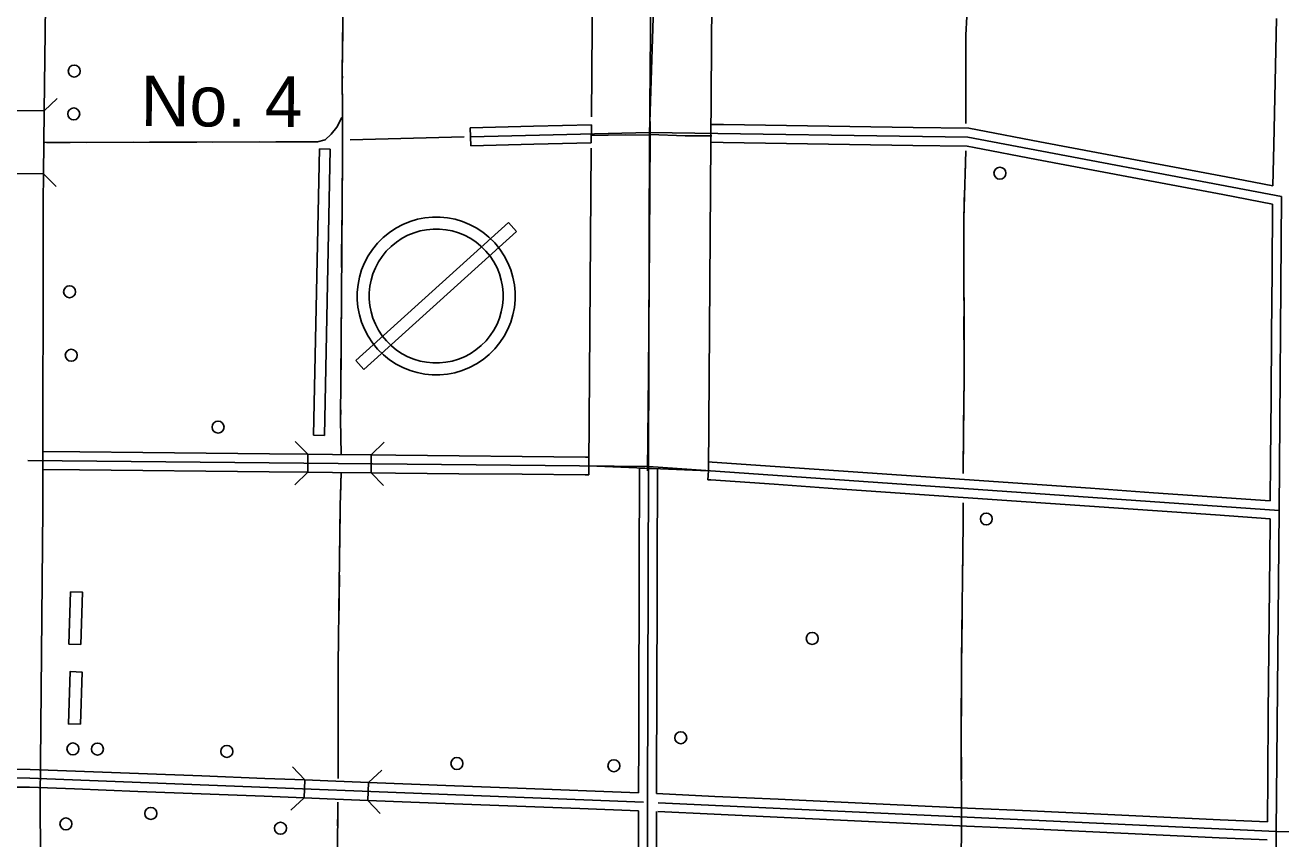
# Model space of a CAD drawing. Extents: x -4306 to 3843, y 131 to 8341.
# Drawn here: x -255 to 1424, y 1864 to 2952 of the extents above; entities that cross this region are included whole.
import ezdxf

# ---------------------------------------------------------------- set-up
doc = ezdxf.new("R2010")
doc.units = 0
for name, color, linetype in [('10', 7, 'Continuous'), ('31', 7, 'Continuous'), ('32', 7, 'Continuous'), ('33', 7, 'Continuous'), ('34', 7, 'Continuous'), ('38', 7, 'Continuous'), ('46', 7, 'Continuous'), ('52', 7, 'Continuous'), ('53', 7, 'Continuous'), ('55', 7, 'Continuous'), ('56', 7, 'Continuous'), ('57', 7, 'Continuous'), ('58', 7, 'Continuous'), ('62', 7, 'Continuous')]:
    doc.layers.add(name, color=color, linetype=linetype)

msp = doc.modelspace()

# ---------------------------------------------------------------- linework, layer by layer
at = {"layer": '10'}
for p, q in [((-229, 2837.7), (-269, 2838.1)), ((-229.9, 2753.2), (-229, 2837.2)), ((-269.9, 2754), (-229.9, 2753.6))]:
    msp.add_line(p, q, dxfattribs=at)
for points in [[(-226.6, 3049.5), (-229, 2837.2)], [(-229.9, 2753.2), (-230.3, 2716.3), (-231, 2305.2), (-234.2, 1917.5), (-233.4, 1758), (-238.7, 1599), (-240.3, 1434.8), (-238.9, 1200.9), (-242.2, 1053.5), (-244.1, 861.8), (-243.5, 732.4), (-254.4, 657.4), (-262.5, 621.4), (-265.5, 597.6), (-272.4, 440.2), (-274.5, 304.9), (-274.4, 293.9)]]:
    msp.add_lwpolyline(points, dxfattribs=at)
at = {"layer": '31'}
for p, q in [((566.1, 2166.4), (566.3, 2250.9)), ((566.3, 2250.9), (566.3, 2250.9)), ((590.1, 2166.3), (590.3, 2250.8)), ((565.9, 2081.9), (566.1, 2166.4)), ((589.9, 2081.9), (590.1, 2166.3)), ((-247.9, 1956.9), (-272.1, 1957.2)), ((-187.4, 1954.6), (-247.9, 1956.9)), ((-102.9, 1951.3), (-187.4, 1954.6)), ((-248.5, 1932.9), (-272.4, 1933.2)), ((-188.3, 1930.6), (-248.5, 1932.9)), ((-103.9, 1927.3), (-188.3, 1930.6)), ((65.9, 1944.7), (65.9, 1944.7)), ((119.3, 1942.7), (65.9, 1944.7)), ((118.4, 1918.7), (119.3, 1942.7)), ((150.3, 1941.5), (119.3, 1942.7)), ((204.6, 1939.4), (150.3, 1941.5)), ((203.6, 1915.4), (204.5, 1939.4)), ((204.5, 1939.4), (319.2, 1934.9)), ((319.2, 1934.9), (403.6, 1931.7)), ((565.4, 1925.4), (403.6, 1931.7)), ((118.6, 1918.7), (65, 1920.8)), ((149.4, 1917.5), (118.4, 1918.7)), ((203.6, 1915.4), (149.4, 1917.5)), ((318.3, 1910.9), (203.6, 1915.4)), ((402.7, 1907.7), (318.3, 1910.9)), ((487.1, 1904.4), (402.7, 1907.7)), ((565.4, 1901.4), (487.1, 1904.4))]:
    msp.add_line(p, q, dxfattribs=at)
for points in [[(579.9, 2808.9), (592.5, 3199.4), (592.3, 3209.3), (595.4, 3430.4)], [(577.4, 1912.9), (578.6, 2361.9), (579.9, 2808.9)], [(566.6, 2335.4), (566.6, 2360)], [(566.6, 2360), (590.6, 2359), (590.6, 2335.3)], [(566.3, 2250.9), (566.6, 2335.4)], [(590.6, 2335.3), (590.3, 2250.8)], [(565.6, 1997.4), (565.9, 2081.9)], [(589.9, 2081.9), (589.4, 1924.4)], [(565.4, 1925.4), (565.6, 1997.4)], [(-18.5, 1948), (-102.9, 1951.3)], [(65.9, 1944.7), (-18.5, 1948)], [(-103.9, 1927.3), (-19.4, 1924)], [(-19.4, 1924), (65, 1920.8)]]:
    msp.add_lwpolyline(points, dxfattribs=at)
at = {"layer": '32'}
for p, q in [((1418.2, 2961.3), (1416.3, 2876.8)), ((1416.3, 2876.8), (1414.4, 2792.4)), ((340.7, 2802.9), (579.9, 2808.9)), ((579.9, 2808.9), (1005.6, 2802.5)), ((662.1, 2819.7), (678.8, 2819.4)), ((678.8, 2819.4), (763.3, 2818.2)), ((763.3, 2818.2), (847.7, 2816.9)), ((847.7, 2816.9), (932.2, 2815.6)), ((932.2, 2815.6), (1006.8, 2814.5)), ((1006.8, 2814.5), (1018.6, 2812.2)), ((1018.6, 2812.2), (1101.6, 2796.5)), ((662, 2795.7), (678.4, 2795.4)), ((678.4, 2795.4), (762.9, 2794.2)), ((762.9, 2794.2), (847.4, 2792.9)), ((847.4, 2792.9), (931.9, 2791.6)), ((931.9, 2791.6), (1004.4, 2790.5)), ((1004.4, 2790.5), (1014.1, 2788.6)), ((1005.6, 2802.5), (1424.9, 2723.1)), ((1014.1, 2788.6), (1097.1, 2772.9)), ((1101.6, 2796.5), (1184.6, 2780.8)), ((1414.4, 2792.4), (1413.2, 2737.5)), ((1097.1, 2772.9), (1180.1, 2757.2)), ((1184.6, 2780.8), (1267.6, 2765.1)), ((1180.1, 2757.2), (1263.1, 2741.5)), ((1267.6, 2765.1), (1350.6, 2749.4)), ((1263.1, 2741.5), (1346.2, 2725.8)), ((1350.6, 2749.4), (1413.2, 2737.5)), ((1346.2, 2725.8), (1412.8, 2713.1)), ((1424.9, 2723.1), (1421.6, 2303.3)), ((1412.8, 2713.1), (1412.1, 2623.2)), ((1412.1, 2623.2), (1411.4, 2538.8)), ((1411.4, 2538.8), (1410.8, 2454.3)), ((1410.8, 2454.3), (1410.1, 2369.8)), ((578.6, 2361.9), (-250.7, 2370.1)), ((-181.5, 2381.5), (-230.8, 2381.9)), ((-97, 2380.6), (-181.5, 2381.5)), ((-12.5, 2379.8), (-97, 2380.6)), ((71.9, 2378.9), (-12.5, 2379.8)), ((123.4, 2378.4), (71.9, 2378.9)), ((123.4, 2378.4), (123.2, 2354.4)), ((156.4, 2378.1), (123.4, 2378.4)), ((208.1, 2377.6), (156.4, 2378.1)), ((208.1, 2377.6), (207.9, 2353.6)), ((240.9, 2377.3), (208.1, 2377.6)), ((325.4, 2376.4), (240.9, 2377.3)), ((409.9, 2375.6), (325.4, 2376.4)), ((494.4, 2374.7), (409.9, 2375.6)), ((499, 2374.7), (494.4, 2374.7)), ((499, 2374.7), (498.9, 2362.7)), ((658.8, 2368.4), (658.7, 2356.3)), ((663.8, 2368), (658.8, 2368.4)), ((748.1, 2362.1), (663.8, 2368)), ((1410.1, 2369.8), (1409.7, 2316.2)), ((-181.8, 2357.5), (-230.9, 2357.9)), ((-97.3, 2356.6), (-181.8, 2357.5)), ((-12.8, 2355.8), (-97.3, 2356.6)), ((71.7, 2354.9), (-12.8, 2355.8)), ((123.2, 2354.4), (71.7, 2354.9)), ((156.2, 2354.1), (123.2, 2354.4)), ((207.9, 2353.6), (156.2, 2354.1)), ((240.7, 2353.3), (207.9, 2353.6)), ((325.2, 2352.4), (240.7, 2353.3)), ((409.6, 2351.6), (325.2, 2352.4)), ((494.1, 2350.7), (409.6, 2351.6)), ((498.8, 2350.7), (494.1, 2350.7)), ((498.9, 2362.7), (498.8, 2350.7)), ((1421.6, 2303.3), (578.6, 2361.9)), ((658.7, 2356.3), (657.9, 2344.4)), ((832.4, 2356.3), (748.1, 2362.1)), ((916.7, 2350.4), (832.4, 2356.3)), ((1001, 2344.6), (916.7, 2350.4)), ((662.2, 2344.1), (657.9, 2344.4)), ((746.5, 2338.2), (662.2, 2344.1)), ((830.8, 2332.3), (746.5, 2338.2)), ((1085.3, 2338.7), (1001, 2344.6)), ((1169.6, 2332.9), (1085.3, 2338.7)), ((915, 2326.5), (830.8, 2332.3)), ((999.3, 2320.6), (915, 2326.5)), ((1083.6, 2314.8), (999.3, 2320.6)), ((1253.8, 2327), (1169.6, 2332.9)), ((1338.1, 2321.1), (1253.8, 2327)), ((1409.7, 2316.2), (1338.1, 2321.1)), ((1167.9, 2308.9), (1083.6, 2314.8)), ((1252.2, 2303.1), (1167.9, 2308.9)), ((1336.5, 2297.2), (1252.2, 2303.1)), ((1421.6, 2303.3), (1417.7, 1873.9)), ((1409.5, 2292.1), (1336.5, 2297.2)), ((1409.4, 2285.3), (1408.7, 2200.8)), ((1409.5, 2292.1), (1409.4, 2285.3)), ((1408.7, 2200.8), (1407.9, 2116.3)), ((1407.9, 2116.3), (1407.1, 2031.9)), ((1407.1, 2031.9), (1406.3, 1947.4)), ((-248.2, 1944.9), (-1090.3, 1954.4)), ((1406.3, 1947.4), (1405.8, 1886.5)), ((572, 1913.1), (-248.2, 1944.9)), ((667.4, 1920.7), (589.4, 1924.4)), ((751.8, 1916.8), (667.4, 1920.7)), ((836.2, 1912.9), (751.8, 1916.8)), ((565.4, 1901.4), (565.4, 1828.4)), ((577.4, 1912.9), (577.5, 1509.2)), ((589.4, 1900.3), (589.4, 1828.4)), ((666.3, 1896.8), (591.1, 1900.3)), ((1417.7, 1873.9), (591.7, 1912.3)), ((750.7, 1892.9), (666.3, 1896.8)), ((920.6, 1909), (836.2, 1912.9)), ((1005, 1905.1), (920.6, 1909)), ((1089.4, 1901.2), (1005, 1905.1)), ((1173.8, 1897.2), (1089.4, 1901.2)), ((1258.2, 1893.3), (1173.8, 1897.2)), ((835.1, 1888.9), (750.7, 1892.9)), ((919.5, 1885), (835.1, 1888.9)), ((1003.9, 1881.1), (919.5, 1885)), ((1088.3, 1877.2), (1003.9, 1881.1)), ((1342.6, 1889.4), (1258.2, 1893.3)), ((1405.8, 1886.5), (1342.6, 1889.4)), ((1172.7, 1873.3), (1088.3, 1877.2)), ((1257.1, 1869.4), (1172.7, 1873.3)), ((1341.5, 1865.4), (1257.1, 1869.4)), ((1405.6, 1862.5), (1341.5, 1865.4)), ((1417.7, 1873.9), (1414, 1460.6)), ((1849.1, 1865.2), (1417.7, 1873.9))]:
    msp.add_line(p, q, dxfattribs=at)
at = {"layer": '33'}
for p, q in [((582.4, 3039.2), (580.3, 2843.7)), ((580.3, 2843.7), (580.7, 2804)), ((580.7, 2804), (579.8, 2663.9)), ((580.7, 2806.1), (627.8, 2804.5)), ((627.8, 2804.5), (663.4, 2804.3)), ((579.8, 2663.9), (578.5, 2485.6)), ((578.5, 2485.6), (577.4, 2356.1))]:
    msp.add_line(p, q, dxfattribs=at)
at = {"layer": '34'}
for p, q in [((547.4, 2805.6), (502.1, 2804.7)), ((580.6, 2805.3), (547.4, 2805.6))]:
    msp.add_line(p, q, dxfattribs=at)
at = {"layer": '38'}
for points in [[(106.6, 2395.6), (123.4, 2378.4)], [(208.1, 2377.6), (225.2, 2394.4)], [(123.2, 2354.4), (106.1, 2337.6)], [(224.7, 2336.4), (207.9, 2353.6)], [(103, 1960.3), (119.3, 1942.7)], [(204.5, 1939.4), (222.1, 1955.7)], [(118.4, 1918.7), (100.8, 1902.4)], [(219.9, 1897.8), (203.6, 1915.4)]]:
    msp.add_lwpolyline(points, dxfattribs=at)
at = {"layer": '46'}
for p, q in [((340.4, 2814.9), (424.9, 2817.1)), ((341, 2790.9), (340.4, 2814.9)), ((424.9, 2817.1), (502.3, 2819)), ((502.1, 2795), (502.3, 2819)), ((341, 2790.9), (425.5, 2793.1)), ((425.5, 2793.1), (502.1, 2795))]:
    msp.add_line(p, q, dxfattribs=at)
at = {"layer": '52'}
msp.add_line((179.8, 2798.8), (332.3, 2802.8), dxfattribs=at)
at = {"layer": '53'}
msp.add_line((658.7, 2356.3), (498.9, 2362.7), dxfattribs=at)
for points in [[(506.8, 3428.7), (502.3, 2829.6)], [(658.7, 2356.3), (666.6, 3426.2)], [(502, 2788), (498.9, 2362.7)]]:
    msp.add_lwpolyline(points, dxfattribs=at)
at = {"layer": '55'}
msp.add_lwpolyline([(168.6, 2828.8), (161.9, 2815.8), (154.6, 2806.7), (146.3, 2799), (136.1, 2796.4), (-228.2, 2795.5)], dxfattribs=at)
at = {"layer": '56'}
for points in [[(171.8, 3589.1), (171.4, 3563.3), (171.3, 3496.1), (171, 3432.6), (172.2, 3333.7), (171.4, 3260.5), (172.2, 3153.3), (173.3, 3061.5), (170.6, 2998.5), (169.4, 2887.7), (169.9, 2831.1), (169.7, 2779.7), (168.3, 2589.1), (167.2, 2425), (167.8, 2378)], [(1030.8, 3158.8), (1030.7, 3156.5), (1027.1, 3133.1), (1021.8, 3087.5), (1013.7, 3036.4), (1005.5, 2989.4), (1003, 2938.9), (1002.7, 2821)], [(170, 2944.9), (169.4, 2887.7), (169.5, 2881.5)], [(1003.1, 2939), (1003, 2938.9), (1002.9, 2875.6)], [(169.6, 2860.4), (169.9, 2831.1), (169.8, 2797.1)], [(1002.8, 2854.5), (1002.7, 2821)], [(-225.8, 2795.5), (136.1, 2796.4), (146.3, 2799), (154.6, 2806.7), (161.9, 2815.8), (168.6, 2828.8)], [(-225.8, 2795.5), (-194.1, 2795.5)], [(-173, 2795.6), (-109.6, 2795.8)], [(-88.5, 2795.8), (-25.1, 2796)], [(-4, 2796), (59.4, 2796.2)], [(80.5, 2796.3), (136.1, 2796.4), (143.6, 2798.3)], [(169.7, 2775.9), (169.2, 2712.6)], [(1002.6, 2784.5), (1000.2, 2693.2), (1000.5, 2483.8), (999.4, 2362.3), (999.4, 2352.5)], [(1002.6, 2784.5), (1001.7, 2752.8)], [(1001.2, 2731.7), (1000.2, 2693.2), (1000.2, 2668.3)], [(169, 2691.4), (168.5, 2628.1)], [(1000.2, 2647.2), (1000.3, 2583.9)], [(168.4, 2607), (168.3, 2589.1), (168.2, 2575.3)], [(168.2, 2575.3), (168, 2543.6)], [(1000.3, 2562.7), (1000.4, 2499.4)], [(167.8, 2522.5), (167.4, 2459.1)], [(1000.4, 2478.2), (999.9, 2414.9)], [(167.3, 2438), (167.2, 2425), (167.8, 2378)], [(999.7, 2393.8), (999.4, 2362.3), (999.4, 2352.5)], [(167.7, 2354), (166.6, 2309.5), (164.1, 2097.3), (163.7, 1945.2), (163.7, 1944.6)], [(167.7, 2354), (166.9, 2322.3)], [(166.5, 2301.2), (165.8, 2237.8)], [(999.3, 2313.2), (999.2, 2286.4), (997.2, 2101.7), (996.6, 2003.3), (996.9, 1879.7), (995.5, 1749.8), (995.1, 1656.3), (994.6, 1501.8), (994.6, 1500.8)], [(999.3, 2313.2), (999.2, 2286.4), (999.2, 2281.5)], [(999, 2260.4), (998.3, 2197)], [(165.5, 2216.7), (164.8, 2153.3)], [(998, 2175.9), (997.4, 2112.5)], [(164.5, 2132.2), (164.1, 2097.3), (164, 2068.9)], [(997.2, 2091.4), (996.8, 2028.1)], [(164, 2047.7), (163.8, 1984.4)], [(996.7, 2006.9), (996.6, 2003.3), (996.8, 1943.6)], [(163.7, 1963.2), (163.7, 1945.2), (163.7, 1944.6)], [(163.4, 1912.9), (163.3, 1899.3), (162.2, 1772.3), (161.1, 1685.1), (157.9, 1537.8)], [(163.4, 1912.9), (163.3, 1899.3), (163.1, 1881.2)]]:
    msp.add_lwpolyline(points, dxfattribs=at)
at = {"layer": '57'}
for points in [[(-180, 2123.8), (-196, 2124.4), (-193.7, 2194.3), (-177.7, 2193.8)], [(-180.7, 2017.2), (-196.7, 2017.7), (-194.4, 2087.7), (-178.4, 2087.1)]]:
    msp.add_lwpolyline(points, close=True, dxfattribs=at)
for centre in [(-188.9, 2891), (-189.5, 2833.7), (1048.4, 2754.4), (-195.1, 2595.8), (-192.8, 2510.8), (3.3, 2414.7), (1030.2, 2291.8), (797.5, 2132), (621.7, 1999.2), (-190.6, 1984.2), (-157.8, 1984), (15.1, 1980.9), (322.6, 1964.7), (532.4, 1961.7), (-86.5, 1897.9), (-200, 1883.9), (86.8, 1878.1)]:
    msp.add_circle(centre, 8, dxfattribs=at)
at = {"layer": '58'}
for p, q in [((138.9, 2786.9), (130.9, 2404)), ((138.9, 2786.9), (153.4, 2786.6)), ((153.4, 2786.6), (145.4, 2403.7)), ((391.5, 2688.4), (187.6, 2503.6)), ((402.2, 2676.6), (391.5, 2688.4)), ((198.3, 2491.7), (402.2, 2676.6)), ((187.6, 2503.6), (198.3, 2491.7)), ((145.4, 2403.7), (130.9, 2404))]:
    msp.add_line(p, q, dxfattribs=at)
for radius, start, end in [(105.6, 42.2006, 222.2006), (89.6, 42.2006, 222.2006), (105.6, 222.2006, 42.2006), (89.6, 222.2006, 42.2006)]:
    msp.add_arc((294.9, 2590.1), radius, start, end, dxfattribs=at)
at = {"layer": '62'}
for p, q in [((-249, 2837.9), (-249, 2837.9)), ((-249.9, 2753.8), (-249.9, 2753.8))]:
    msp.add_line(p, q, dxfattribs=at)
for points in [[(-229, 2837.7), (-211.8, 2854.5)], [(-213.1, 2736.4), (-229.9, 2753.6)]]:
    msp.add_lwpolyline(points, dxfattribs=at)

# ---------------------------------------------------------------- texts
at = {"layer": '56'}
msp.add_text('No. 4', height=67.59, rotation=359.6372, dxfattribs=at).set_placement((-100.2, 2817.5))

doc.saveas('drawing.dxf')
